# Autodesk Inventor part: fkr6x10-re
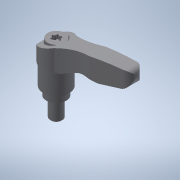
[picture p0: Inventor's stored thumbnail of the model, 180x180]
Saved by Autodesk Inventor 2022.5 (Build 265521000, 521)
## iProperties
Created: 2017-09
Part Number: fkr6x10-re
Material: 一般
Document SubType Name: Modeling
Designer: imaocorp
Density: 1 g/cm^3
Appearance: 既定
Author: imaocorp
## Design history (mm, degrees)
node "fkr6x10-re.x_t1"
node "fkr6x10-re"
node "Base1"
